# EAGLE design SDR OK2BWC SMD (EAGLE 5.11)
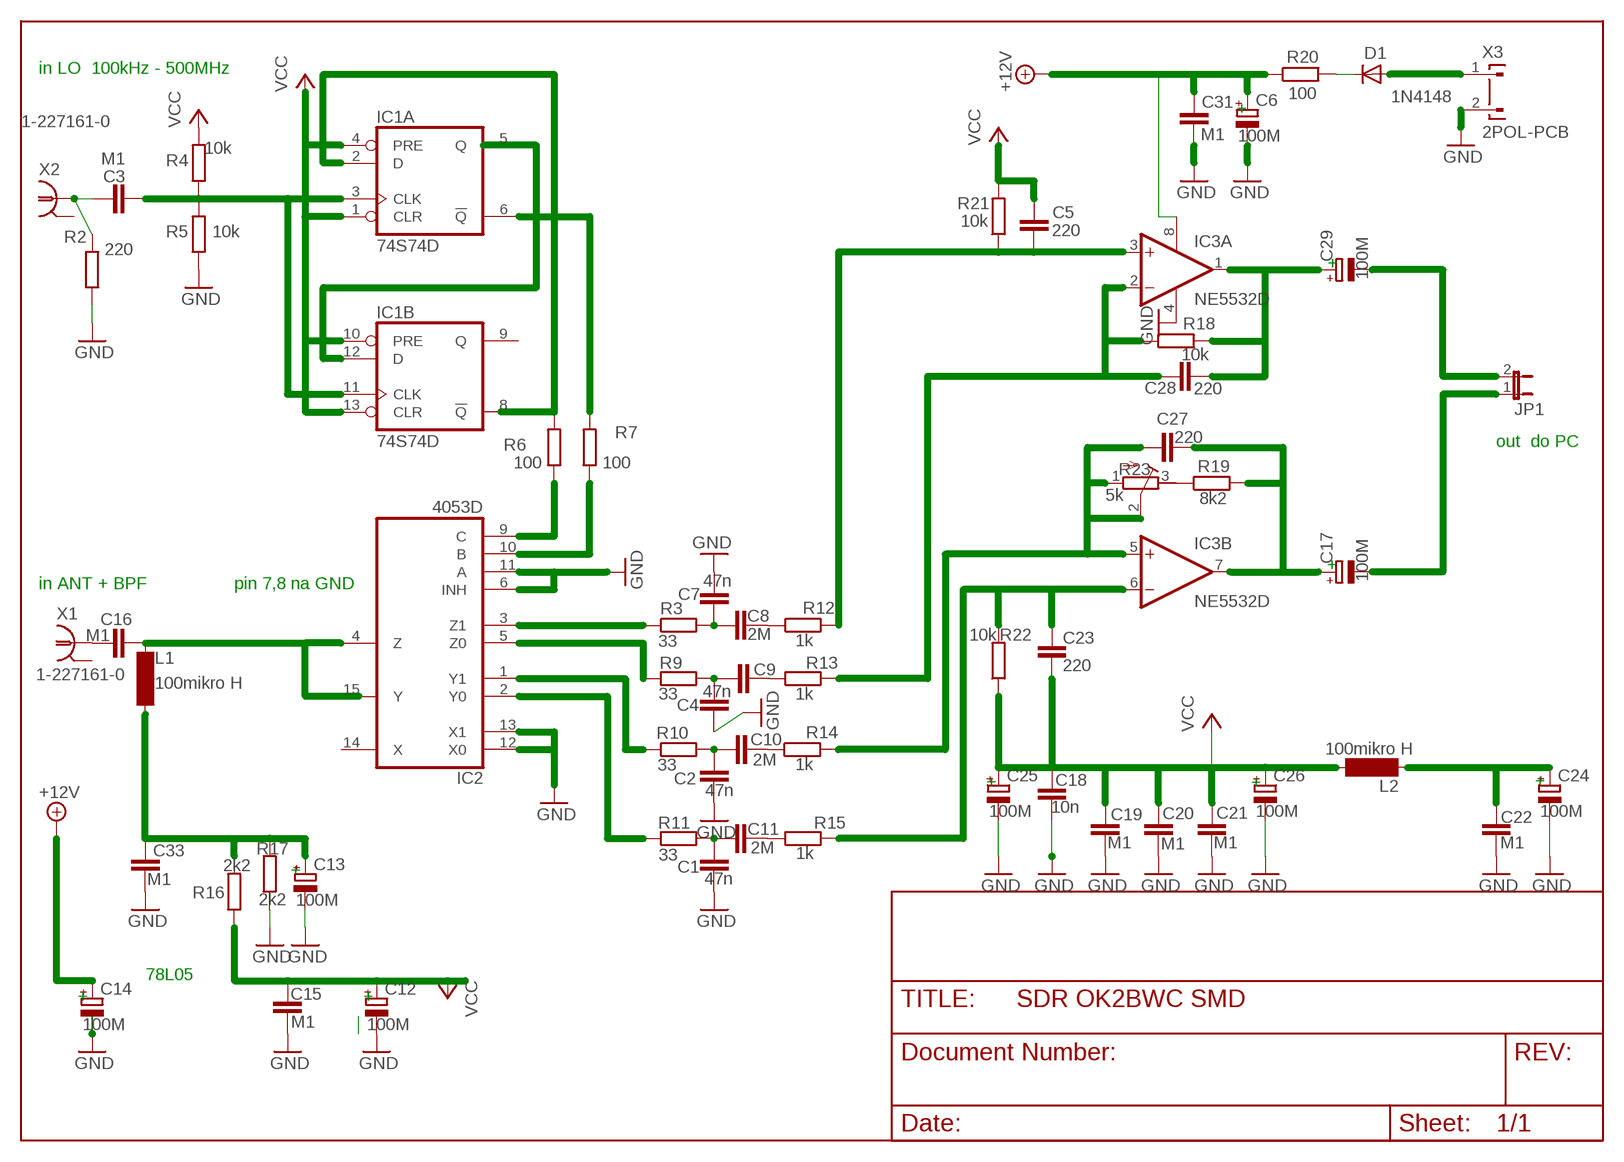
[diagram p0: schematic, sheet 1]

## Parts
C1  47n  C-EUC4532  [C4532]
C2  47n  C-EUC4532  [C4532]
C3  M1  C-EUC4532  [C4532]
C4  47n  C-EUC4532  [C4532]
C5  220  C-EUC4532  [C4532]
C6  100M  CPOL-EU085CS-1AR  [085CS_1AR]
C7  47n  C-EUC4532  [C4532]
C8  2M  C-EUC4532  [C4532]
C9  2M  C-EUC4532  [C4532]
C10  2M  C-EUC4532  [C4532]
C11  2M  C-EUC4532  [C4532]
C12  100M  CPOL-EU085CS-1AR  [085CS_1AR]
C13  100M  CPOL-EU085CS-1AR  [085CS_1AR]
C14  100M  CPOL-EU085CS-1AR  [085CS_1AR]
C15  M1  C-EUC2220K  [C2220K]
C16  M1  C-EUC4532  [C4532]
C17  100M  CPOL-EU085CS-1AR  [085CS_1AR]
C18  10n  C-EUC4532  [C4532]
C19  M1  C-EUC4532  [C4532]
C20  M1  C-EUC4532  [C4532]
C21  M1  C-EUC4532  [C4532]
C22  M1  C-EUC4532  [C4532]
C23  220  C-EUC4532  [C4532]
C24  100M  CPOL-EU085CS-1AR  [085CS_1AR]
C25  100M  CPOL-EU085CS-1AR  [085CS_1AR]
C26  100M  CPOL-EU085CS-1AR  [085CS_1AR]
C27  220  C-EUC4532  [C4532]
C28  220  C-EUC4532  [C4532]
C29  100M  CPOL-EU085CS-1AR  [085CS_1AR]
C31  M1  C-EUC4532  [C4532]
C33  M1  C-EUC2220K  [C2220K]
D1  1N4148  1N4148DO35-10  [DO35-10]
IC1  74S74D  [SO14]
IC2  4053D  [SO16]
IC3  NE5532D  [SO08]
JP1  JP1E  [JP1]
L1  100mikro H  SM-NE45  [SM-NE45]
L2  100mikro H  SM-NE45  [SM-NE45]
R2  220  R-EU_M3516  [M3516]
R3  33  R-EU_M3516  [M3516]
R4  10k  R-EU_M3516  [M3516]
R5  10k  R-EU_M3516  [M3516]
R6  100  R-EU_M3516  [M3516]
R7  100  R-EU_M3516  [M3516]
R9  33  R-EU_M3516  [M3516]
R10  33  R-EU_M3516  [M3516]
R11  33  R-EU_M3516  [M3516]
R12  1k  R-EU_M3516  [M3516]
R13  1k  R-EU_M3516  [M3516]
R14  1k  R-EU_M3516  [M3516]
R15  1k  R-EU_M3516  [M3516]
R16  2k2  R-EU_M3516  [M3516]
R17  2k2  R-EU_M3516  [M3516]
R18  10k  R-EU_M3516  [M3516]
R19  8k2  R-EU_M3516  [M3516]
R20  100  R-EU_M3516  [M3516]
R21  10k  R-EU_M3516  [M3516]
R22  10k  R-EU_M3516  [M3516]
R23  5k  R-TRIMM4G/J  [RTRIM4G/J]
X1  1-227161-0  [AMP_227161]
X2  1-227161-0  [AMP_227161]
X3  2POL-PCB  [2POL-PCB]

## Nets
+12V: C6.+ C14.+ C31.1 IC3.8(P:V+) R20.1
GND: C1.2 C2.2 C4.2 C6.- C7.1 C12.- C13.- C14.- C15.2 C18.2 C19.2 C20.2 C21.2 C22.2 C24.- C25.- C26.- C31.2 C33.2 IC2.6(INH) IC2.11(A) IC2.13(X1) IC3.4(P:V-) R2.1 R5.1 R17.1 X3.2
N$1: C3.1 R2.2 X2.1
N$2: IC1.5(A:Q) IC1.12(B:D)
N$3: C16.1 X1.1
N$4: C3.2 IC1.3(A:CLK) IC1.11(B:CLK) R4.1 R5.2
N$5: C16.2 IC2.4(Z) L1.2
N$6: IC2.9(C) R6.1
N$7: IC2.10(B) R7.1
N$8: IC1.6(A:!Q) R7.2
N$9: IC1.2(A:D) IC1.8(B:!Q) R6.2
N$10: C28.2 C29.+ IC3.1(A:OUT) R18.2
N$11: C17.+ C27.2 R19.2
N$12: C29.- JP1.2
N$13: C17.- JP1.1
N$14: D1.A X3.1
N$89: IC2.12(X0)
N$90: C7.2 C8.1 R3.2
N$91: C1.1 C11.1 R11.2
N$92: C2.1 C10.1 R10.2
N$93: C4.1 C9.1 R9.2
N$94: IC2.3(Z1) R3.1
N$95: IC2.5(Z0) R9.1
N$96: IC2.1(Y1) R10.1
N$97: IC2.2(Y0) R11.1
N$98: C8.2 R12.1
N$99: C9.2 R13.1
N$100: C10.2 R14.1
N$101: C11.2 R15.1
N$102: C13.+ C33.1 L1.1 R16.2 R17.2
N$103: D1.C R20.2
N$104: C28.1 IC3.2(A:-IN) R13.2 R18.1
N$106: R19.1 R23.3(A)
N$107: C27.1 R14.2 R23.1(E) R23.2(S)
N$108: C23.1 IC3.6(B:-IN) R15.2 R22.2
N$110: C22.1 C24.+ L2.1
N$111: C5.2 IC3.3(A:+IN) R12.2 R21.1
VCC: C5.1 C12.+ C15.1 C18.1 C19.1 C20.1 C21.1 C23.2 C25.+ C26.+ IC1.1(A:CLR) IC1.4(A:PRE) IC1.10(B:PRE) IC1.13(B:CLR) L2.2 R4.2 R16.1 R21.2 R22.1
Unconnected: IC1.9(B:Q) IC2.14(X) IC2.15(Y) IC3.5(B:+IN) IC3.7(B:OUT)

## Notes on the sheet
- in LO  100kHz - 500MHz
- +
- +
- out  do PC
- +
- in ANT + BPF | pin 7,8 na GND
- + | + | +
- +
- 78L05
- + | +

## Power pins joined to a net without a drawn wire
GND: IC1.7(P:GND) IC2.8(GND) X1.2(GND) X2.2(GND)
VCC: IC1.14(P:VCC) IC2.16(VCC)
VEE: IC2.7(VEE)

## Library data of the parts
C1-C5 C7-C11 C16 C18-C23 C27 C28 C31 = resistor:C-EU: CAPACITOR, European symbol
C6 C12-C14 C17 C24-C26 C29 = rcl:CPOL-EU: POLARIZED CAPACITOR, European symbol
C15 C33 = rcl:C-EU: CAPACITOR, European symbol
D1 = diode:1N4148: DIODE
IC1 = 74xx-eu:74*74: Dual D type positive edge triggered FLIP FLOP, preset and clear
IC2 = 40xx:4053: Triple 2-channel ANALOG MULTIPLEXER
IC3 = linear:NE5532: AUDIO AMPLIFIER
JP1 = jumper:JP1E: JUMPER
L1 L2 = inductor-neosid:SM-NE45: INDUCTOR; OC_FARNELL: unknown; OC_NEWARK: unknown
R2-R7 R9-R22 = resistor:R-EU_: RESISTOR, European symbol
R23 = rcl:R-TRIMM: Trimm resistor
X1 X2 = con-coax:?227161*: JACK, RIGHT ANGLE, 50 OHM, PCB, BNC; MF: TYCO ELECTRONICS; MPN: 1-227161; OC_FARNELL: unknown; OC_NEWARK: 33B3200
X3 = con-friwo:2POL-PCB: PCB SUPPLY CONNECTOR; OC_FARNELL: unknown; OC_NEWARK: unknown

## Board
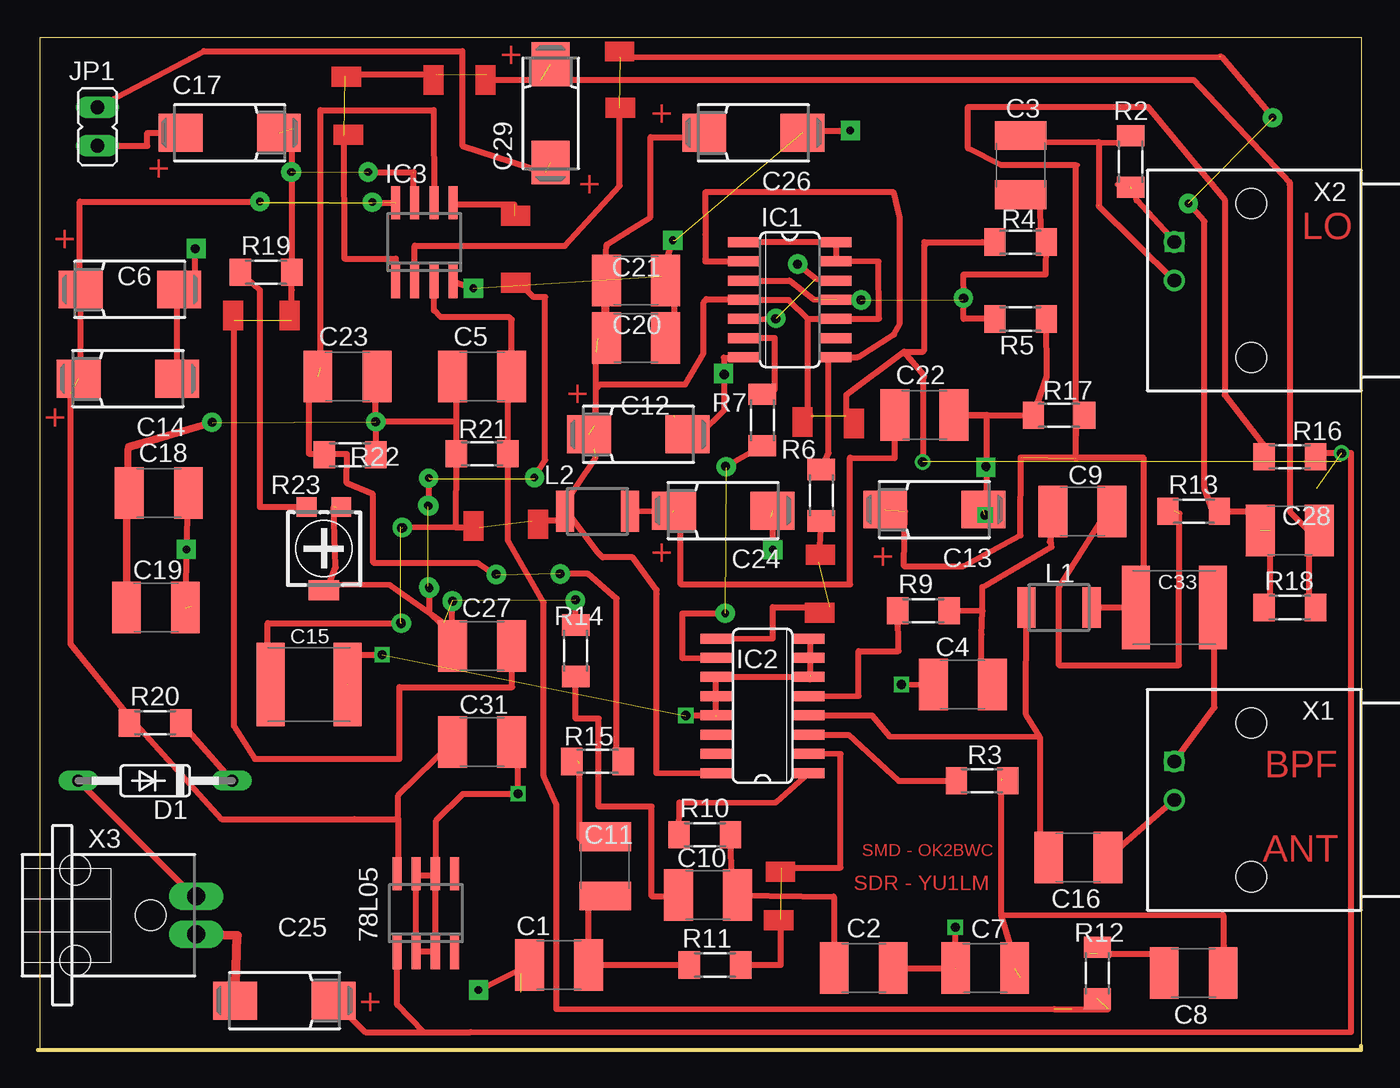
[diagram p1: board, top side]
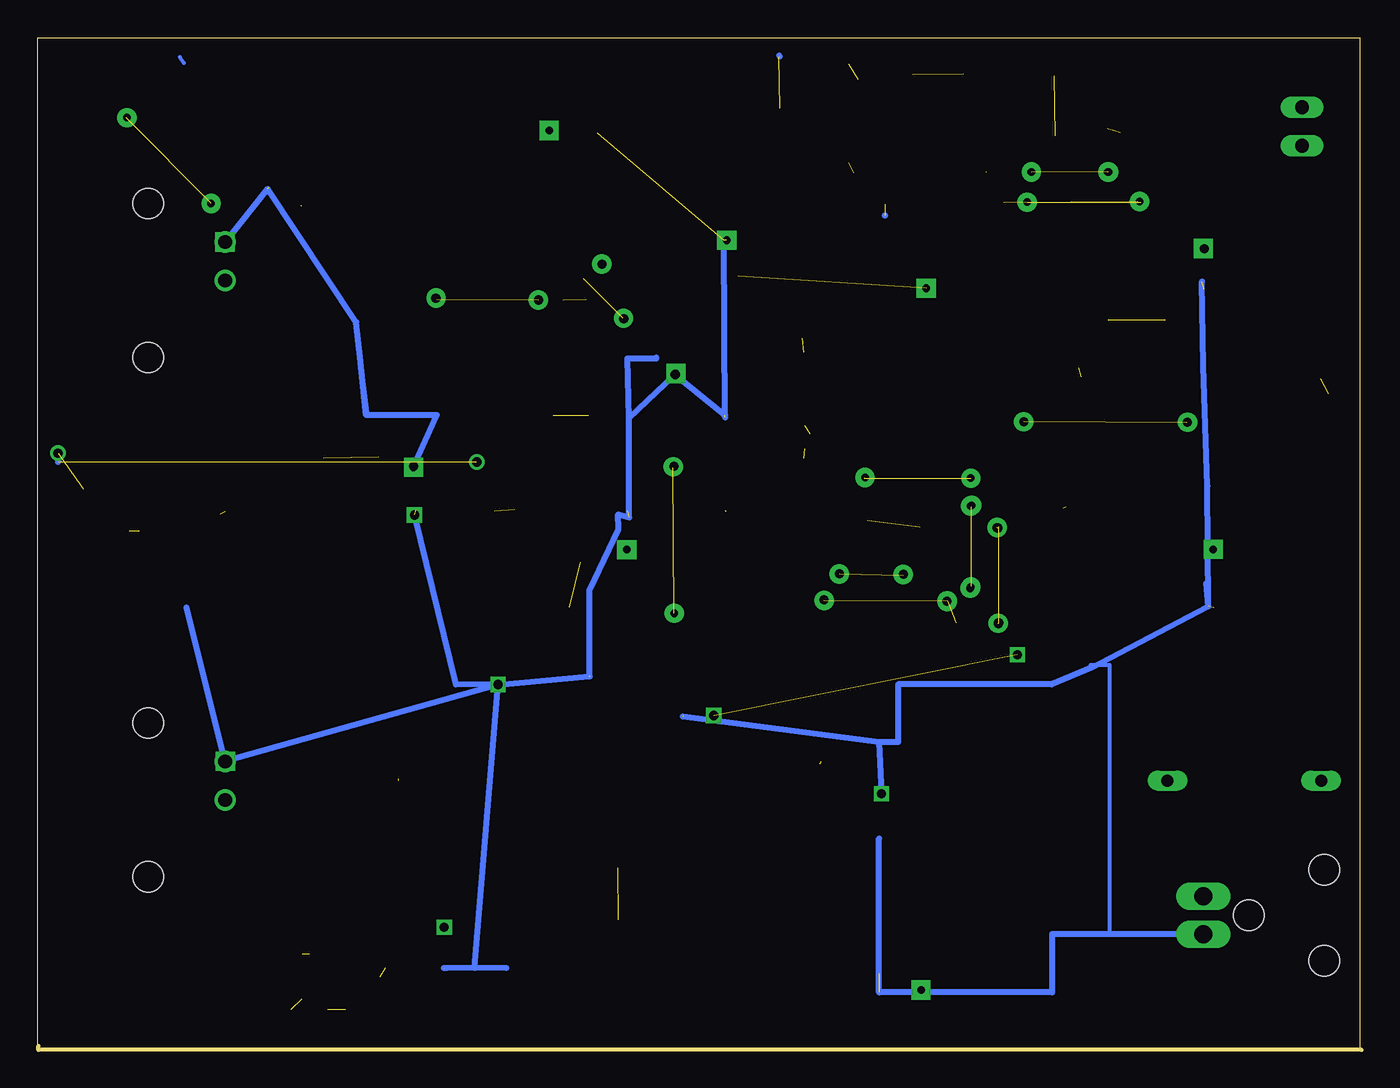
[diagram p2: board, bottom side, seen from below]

Size 87.43 x 66.82 mm. Coordinates in mm from the lower left corner, seen from the top.
Outline: 87.43,0 87.43,66.82 0.13,66.82 0.13,0
Outline: 0,0 87.39,0 87.39,0.26
Copper layers (1*16): Top 0.035mm / dielectric 1.5mm / Bottom 0.035mm
Design rules "default": minimum track width 10mil, minimum drill 24mil, track to track 8mil, track to pad 8mil, pad to pad 8mil, via to via 8mil, smd to smd 8mil, copper to edge 40mil, drill to drill 8mil, minimum pad ring 10mil, minimum via ring 8mil, stop-mask expansion 4mil, vias tented up to drill 0mil, thermal gap 10mil

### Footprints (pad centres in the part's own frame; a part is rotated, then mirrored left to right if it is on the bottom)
SO8 = smd 0.6 x 2.2: 1 -1.905,-2.6; 2 -0.635,-2.6; 3 0.635,-2.6; 4 1.905,-2.6; 5 1.905,2.6; 6 0.635,2.6; 7 -0.635,2.6; 8 -1.905,2.6
C4532 = smd 1.9 x 3.4: 1 -1.95,0; 2 1.95,0
085CS_1AR = smd 2.9 x 2.5: + 3.25,0; - -3.25,0
C2220K = smd 1.85 x 5.5: 1 -2.55,0; 2 2.55,0
DO35-10 = drill 0.813 long: A 5.08,0; C -5.08,0
SO14 = smd 0.66 x 2.032: 1 -3.81,-3.073; 2 -2.54,-3.073; 3 -1.27,-3.073; 4 0,-3.073; 5 1.27,-3.073; 6 2.54,-3.073; 7 3.81,-3.073; 8 3.81,3.073; 9 2.54,3.073; 10 1.27,3.073; 11 0,3.073; 12 -1.27,3.073; 13 -2.54,3.073; 14 -3.81,3.073
SO16 = smd 0.66 x 2.032: 1 -4.445,-3.073; 2 -3.175,-3.073; 3 -1.905,-3.073; 4 -0.635,-3.073; 5 0.635,-3.073; 6 1.905,-3.073; 7 3.175,-3.073; 8 4.445,-3.073; 9 4.445,3.073; 10 3.175,3.073; 11 1.905,3.073; 12 0.635,3.073; 13 -0.635,3.073; 14 -1.905,3.073; 15 -3.175,3.073; 16 -4.445,3.073
SO08 = smd 0.6 x 2.2: 1 -1.905,-2.6; 2 -0.635,-2.6; 3 0.635,-2.6; 4 1.905,-2.6; 5 1.905,2.6; 6 0.635,2.6; 7 -0.635,2.6; 8 -1.905,2.6
JP1 = drill 0.914 long: 1 0,-1.27; 2 0,1.27
SM-NE45 = smd 1.2 x 2.7: 1 -2.15,0; 2 2.15,0
M3516 = smd 1.4 x 1.8: 1 -1.7,0; 2 1.7,0
RTRIM4G/J = smd 1.3 x 1.3: 1 -1.15,-2.75; 3 1.15,-2.75 | smd 2 x 1.3: 2 0,2.75
AMP_227161 = drill 0.9 pad 1.27 round: 1 0,-5.08; 2 -2.54,-5.08 | hole 2: -5.08,0; 5.08,0
2POL-PCB = drill 1.2 long: 1 -1.25,11.6; 2 1.25,11.6 | hole 2: -3,3.6; 3,3.6; 0,8.6

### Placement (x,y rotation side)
78L05  [SO8]  25.62,9.03 0 top
C1  34.42,5.61 180 top
C2  54.54,5.41 0 top
C3  64.9,58.42 270 top
C4  61.09,24.13 180 top
C5  29.34,44.45 0 top
C6  6.08,50.21 180 top
C7  62.56,5.41 0 top
C8  76.33,5.08 180 top
C9  68.99,35.56 0 top
C10  44.26,10.23 180 top
C11  37.46,12.12 90 top
C12  39.66,40.64 180 top
C13  59.21,35.68 180 top
C14  5.95,44.32 180 top
C15  17.91,24.13 0 top
C16  68.71,12.7 180 top
C17  12.67,60.55 0 top
C18  7.99,36.77 0 top
C19  7.8,29.21 0 top
C20  39.5,46.99 0 top
C21  39.5,50.8 0 top
C22  58.55,41.91 0 top
C23  20.45,44.45 0 top
C24  45.26,35.61 180 top
C25  16.29,3.26 0 top
C26  47.26,60.55 180 top
C27  29.34,26.67 0 top
C28  82.68,34.29 0 top
C29  33.87,61.84 90 top
C31  29.34,20.32 0 top
C33  75.06,29.21 0 top
D1  7.75,17.78 180 top
IC1  49.66,49.53 270 top
IC2  47.87,22.72 90 top
IC3  25.53,53.34 0 top
JP1  3.94,60.96 0 top
L1  67.44,29.21 180 top
L2  36.96,35.56 180 top
R2  72.17,58.65 90 top
R3  62.36,17.78 0 top
R4  64.9,53.34 180 top
R5  64.9,48.26 180 top
R6  51.74,36.62 90 top
R7  47.85,41.59 90 top
R9  58.49,29 0 top
R10  44.05,14.21 0 top
R11  44.72,5.61 180 top
R12  69.98,5.08 270 top
R13  76.33,35.56 0 top
R14  35.52,26.36 90 top
R15  36.96,19.05 0 top
R16  82.68,39.17 180 top
R17  67.44,41.91 0 top
R18  82.68,29.21 0 top
R19  15.08,51.34 0 top
R20  7.75,21.59 0 top
R21  29.34,39.37 180 top
R22  20.62,39.3 180 top
R23  18.9,33.1 180 top
X1  80.14,16.51 270 top
X2  80.14,50.8 270 top
X3  -1.14,8.89 270 top

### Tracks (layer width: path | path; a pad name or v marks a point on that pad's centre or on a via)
+12V  (2 unrouted)
  Top 0.254: C31.1 26.8,20.32 | 5.9,22.17 6.48,21.59 R20.1
  Top 0.406: 2.17,43.32 2.17,26.79 5.9,22.17 12.14,15.24 20.91,15.24 20.94,15.22 23.75,15.22 23.8,15.26 | C14.+ 2.83,44.32 C6.+ 2.78,50.21 2.78,56.01 14.78,56.01 | 23.8,15.26 23.8,12.34 | 23.8,15.26 23.8,16.8 C31.1
GND  (via drill 0.6, 0.61)  (14 unrouted)
  Top 0.254: C20.2 42.04,46.99 | C1.2 31.88,5.08 | C19.2 9.02,29.21 | 9.92,36.9 C18.2 9.87,36.77 | C7.1 59.82,6.35 | R2.1 71.25,57.15 | R5.1 66.17,48.26 | R17.1 66.17,41.91 | 31.71,20.35 C31.2 30.61,20.32 | C4.2 v57.04,24.13 | C33.2
  Top 0.406: 32.55,5.61 C1.2 29.03,3.92 | 31.88,5.08 31.85,6.11 | v57.03,24.12 C4.2 | C33.2 77.7,29.21 77.7,22.62 X1.2 | IC2.8 51.02,27.16 51.02,24.69 51.05,24.49 | 51.05,24.49 50.94,24.49 IC2.6 | IC2.6 51.05,24.62 51.05,24.49 | v31.72,16.92 31.71,20.35 | 42.04,46.99 42.04,50.21 C21.2 41.45,50.82 41.18,51.09 41.94,53.46 | 60.59,8.16 C7.1 C2.2 | R5.1 66.64,44.44 R17.1 C22.2 62.68,41.93 62.68,38.44 | IC3.4 28.76,50.28 | IC2.6 IC2.11 44.79,24.62 44.8,23.48 | 42.7,22.09 44.8,22.09 | 44.8,23.48 44.8,24.67 | 44.8,22.09 IC2.13 | 44.8,22.09 44.8,23.48 | C14.- 9.2,50.21 C6.- 10.39,50.21 v10.39,52.89 | C26.- 50.64,60.68 53.7,60.68 | 45.32,44.52 45.26,44.65 | 45.32,44.52 45.32,42.25 43.71,40.64 C12.- | IC1.7 46.58,45.71 45.31,45.71 45.34,45.68 v45.34,44.59 45.34,44.54 45.32,44.52 | 48.54,33.06 C24.- | 62.68,38.44 62.68,37.02 C13.- | v62.62,38.53 62.23,38.6 62.49,38.34 62.68,38.44 | C19.2 9.92,36.9 | C15.2 20.47,26.1
  Top 0.61: C25.- 13.17,7.55 X3.2
  Bottom 0.254: 16.64,7.62 16.64,7.64 16.64,25.4 17.91,25.4 17.84,25.24 | 66.15,45.72 65.7,42.1
  Bottom 0.406: X3.2 16.64,7.64 20.45,7.64 20.45,3.81 31.88,3.81 31.88,13.97 | 31.88,20.32 v31.72,16.92 | 31.88,20.32 30.61,20.32 30.61,24.13 C15.2 17.84,25.24 10.14,29.28 | 10.14,29.28 10.19,37.23 10.47,45.17 10.54,50.72 | 10.14,29.28 10.27,30.81 | 31.88,20.32 44.83,22.02 | 48.37,41.72 48.37,35.16 49.1,35.36 49.09,34.4 51,30.38 50.98,24.66 v57.03,24.12 | 48.37,41.72 48.5,45.66 46.59,45.66 IC1.7 | 48.37,41.72 v45.34,44.59 42.04,41.91 | v62.62,38.53 61.09,41.91 R17.1 66.15,45.72 66.4,48.06 72.24,56.85 X2.2 | v62.56,35.32 59.82,24.13 v57.03,24.12 | 58.58,5.42 60.42,5.41 C7.1 | v57.03,24.12 X1.2 C33.2 | C2.2 58.58,5.42 | 42.04,41.76 42.13,53.45 | 58.58,5.42 v57.03,24.12
N$1  (1 unrouted)
  Top 0.254: C3.1 64.86,59.96
  Top 0.406: 64.86,59.96 70.07,59.93 | 70.07,59.93 72.07,59.91 R2.2 72.11,60.44 71.78,60.21 71.45,59.84 | 70.07,59.93 70.09,55.76 | 70.05,55.74 X2.1
N$2  (via drill 0.6, 0.61)  (1 unrouted)
  Top 0.254: v48.73,48.27 IC1.5
  Top 0.406: IC1.12 51.38,50.93 v50.17,51.88 | v48.73,48.27 47.25,48.25 48.79,48.3
N$3
  Top 0.254: C16.1 71.25,12.7
  Top 0.406: C16.1 X1.1
N$4  (via drill 0.61)  (2 unrouted)
  Top 0.254: 66.18,56.47 C3.2 | R4.1 66.27,53.34
  Top 0.406: 63.63,48.26 63.63,48.3 63.53,48.4 | 63.53,48.4 63.53,48.2 63.26,48.2 R5.2 61.13,48.26 v61.15,49.63 61.13,51.2 66.56,51.2 R4.1 | 63.53,48.4 63.33,48.6 | IC1.3 49.63,50.8 49.67,50.76 49.7,50.76 51.24,49.56 v54.36,49.51 | 66.27,53.34 66.18,56.47
  Bottom 0.254: v61.15,49.63 61.09,49.53
N$5
  Top 0.254: L1.2 64.9,29.21 | 66.17,12.7 C16.2
  Top 0.406: IC2.4 55.09,22.09 56.25,20.7 66.17,20.67 | 66.17,20.67 66.17,12.7 | 66.17,20.67 65.27,22.16 L1.2 | 64.9,29.21 65.07,29.23
N$6  (1 unrouted)
  Top 0.406: IC2.9 48.54,27.18 48.55,29.23 52.3,29.23 | 51.59,32.19 R6.1
N$7  (1 unrouted)
  Top 0.406: IC2.10 42.57,25.87 42.57,28.83 45.43,28.84 | R7.1 45.5,38.58 45.47,38.55 45.49,38.45
N$8
  Top 0.254: 45.85,46.99 IC1.6
  Top 0.406: 45.85,46.99 48.68,47 48.68,43.61 R7.2
N$9
  Top 0.254: R6.2 52.2,38.15 | 52.2,45.59 IC1.8 53.47,45.72 | 44.08,56.62 44.06,55.14 | 45.85,52.07 IC1.2
  Top 0.406: 45.85,52.07 44.09,52.07 44.08,52.21 44.08,53.82 44.08,56.62 56.53,56.62 56.92,54.94 56.92,47.95 56.54,47.24 54.16,45.75 53.59,45.72 53.47,45.72 | R6.2 52.23,39.41 52.2,45.59
N$10  (3 unrouted)
  Top 0.254: 83.95,29.21 R18.2 | 83.95,34.29 C28.2
  Top 0.406: IC3.1 23.63,52.25 20.25,52.24 20.24,60.37 | 26.29,64.43 20.28,64.43 20.28,64.31 | 82.67,57.3 76.33,64.04 33.22,64.06 29.63,64.06 29.63,64.4 | 82.67,57.3 82.68,57.15 | 83.95,29.21 83.95,34.29 82.7,35.55 82.67,57.3
N$11  (via drill 0.5 pad 1.27)  (5 unrouted)
  Top 0.406: C27.2 31.32,23.96 23.88,23.96 23.88,19.22 14.34,19.22 12.96,21.39 12.96,48.19 | 16.77,48.18 16.77,50.18 R19.2 16.78,60.81 v16.76,57.97 | v21.81,57.96 24.79,57.96 | 24.98,55.95 24.83,55.95 24.83,57.95
  Bottom 0.406: 21.94,58.08 21.94,57.96 v21.81,57.96 21.81,58.08
  other vias: 16.74,57.96
N$12  (1 unrouted)
  Top 0.406: JP1.2 10.98,65.94 28.03,65.95 28.03,59.71 33.52,57.92
N$13
  Top 0.406: C17.- 7.23,60.55 7.23,59.69 JP1.1
N$14
  Top 0.254: X3.1 10.29,10.16
  Top 0.406: 10.29,10.16 D1.A
N$15  (via drill 0.5)
  other vias: 75.06,50.79
N$16  (1 unrouted)
  Top 0.406: 22.09,55.94 23.67,55.95
  Bottom 0.406: 14.57,55.95 14.51,55.99
N$18
  Top 0.406: 75.13,53.33 72.57,56.09 72.3,57.15
N$19  (via drill 0.6)
  other vias: 30.27,31.4
N$20  (1 unrouted)
  Top 0.406: 27.47,55.82 31.47,55.82
  Bottom 0.406: 31.47,55.08 31.5,55.08
N$23  (via drill 0.6)  (1 unrouted)
  other vias: 24.03,34.46 24.09,34.47 24.03,34.46
N$24  (via drill 0.6)
  other vias: 27.38,29.62
N$25  (via drill 0.6)
  other vias: 35.5,29.72
N$26  (via drill 0.5 pad 1.27)
  other vias: 28.76,50.29
N$27  (via drill 0.6)
  other vias: 45.42,38.54
N$28  (via drill 0.5)
  other vias: 75.04,16.53
N$29  (via drill 0.5)
  other vias: 75.14,19.02
N$30  (via drill 0.5)
  other vias: 12.89,17.77
N$31  (via drill 0.5)
  other vias: 2.7,17.77
N$32  (via drill 0.5 pad 1.27)
  other vias: 10.39,10.2
N$33  (via drill 0.5 pad 1.27)
  other vias: 10.39,7.7
N$34  (via drill 0.5 pad 1.27)
  other vias: 24.01,28.17
N$35  (via drill 0.5 pad 1.27)
  other vias: 24.08,34.49
N$36  (via drill 0.5 pad 1.27)
  other vias: 45.4,28.83
N$37  (via drill 0.5 pad 1.27)
  other vias: 45.46,38.51
N$38  (via drill 0.5 pad 1.27)
  other vias: 81.55,61.55
N$39  (via drill 0.5 pad 1.27)
  other vias: 75.99,55.88
N$40  (via drill 0.5 pad 1.27)
  other vias: 61.12,49.64
N$41  (via drill 0.5 pad 1.27)
  other vias: 62.62,38.47
N$42  (via drill 0.5 pad 1.27)
  other vias: 75.04,19.06
N$43  (via drill 0.6)  (1 unrouted)
  Top 0.406: 20.55,26.08 20.47,24.17 20.41,24.2 | v22.73,26.09 21.19,26.1 20.55,26.08 | 20.55,26.08 20.54,26.04
  other vias: 42.79,22.08
N$44  (via drill 0.5 pad 1.27)
  other vias: 45.29,44.66
N$46  (via drill 0.5 pad 1.27)
  other vias: 48.54,33.03
N$47  (via drill 0.5 pad 1.27)
  other vias: 41.94,53.46
N$49  (via drill 0.5 pad 1.27)
  other vias: 50.18,51.89
N$50  (via drill 0.5 pad 1.27)
  other vias: 53.66,60.7
N$51  (via drill 0.5 pad 1.27)
  other vias: 16.72,57.96
N$52  (via drill 0.6)
  other vias: 60.59,8.1
N$54  (via drill 0.5 pad 1.27)
  other vias: 75.08,53.35
N$55  (via drill 0.6 pad 1.27)
  other vias: 11.5,41.45
N$56  (via drill 0.5 pad 1.27)
  other vias: 14.67,56.02
N$57  (via drill 0.5 pad 1.27)
  other vias: 22.1,55.97
N$58  (via drill 0.5 pad 1.27)
  other vias: 25.86,30.48
N$59  (via drill 0.5 pad 1.27)
  other vias: 27.37,29.61
N$60  (via drill 0.5 pad 1.27)
  other vias: 30.28,31.39
N$61  (via drill 0.5 pad 1.27)
  other vias: 34.5,31.42
N$62  (via drill 0.5 pad 1.27)
  other vias: 35.5,29.68
N$63  (via drill 0.5 pad 1.27)
  other vias: 25.81,37.75
N$64  (via drill 0.5 pad 1.27)
  other vias: 32.8,37.79
N$65  (via drill 0.5 pad 1.27)
  other vias: 25.76,35.96
N$66  (via drill 0.5 pad 1.27)
  other vias: 54.38,49.51
N$67  (via drill 0.5 pad 1.27)
  other vias: 48.75,48.3
N$68
  Top 0.406: 26.28,5.74 26.31,5.74 26.28,6.52 25.05,6.52 | 25.05,6.52 24.99,6.52 | 24.99,11.06 24.99,6.58 25.05,6.52
N$69
  Top 0.406: 26.28,11.52 26.28,6.32 26.31,6.29
N$70
  Top 0.406: 26.31,12.45 26.25,11.55 24.96,11.55
N$71
  Top 0.406: 26.31,11.84 26.31,15.16 28.08,16.9 31.76,16.9 | 31.76,16.9 31.76,16.81 31.82,16.81 31.82,16.84 | 31.76,16.9 31.76,16.93
N$90  (2 unrouted)
  Top 0.254: R3.2 63.63,17.78 | 78.29,8.9 78.2,8.96 78.52,5.34 C8.1
  Top 0.406: 63.63,8.92 63.63,8.9 64.87,4.81 | 63.63,8.92 63.64,17.91 | 63.63,8.92 78.29,8.9 78.29,4.41
N$91
  Top 0.254: R11.2 43.08,5.69
  Top 0.406: C11.1 36.37,9.48 C1.1 R11.2
N$92
  Top 0.254: R10.2 45.85,14.31 | 45.85,10.16 45.85,10.96 C10.1
  Top 0.406: C2.1 52.57,10.13 C10.1 | 45.85,10.96 R10.2
N$93
  Top 0.254: 66.77,33.54 66.86,34.47 C9.1 | C4.1 62.36,24.13
  Top 0.406: 62.36,24.13 62.33,27.42 62.39,28.98 | 62.39,28.98 R9.2 | 62.39,28.98 62.37,30.56 66.94,33.22 66.86,34.47
N$94
  Top 0.406: IC2.3 53.55,20.8 56.84,17.77 R3.1
N$95
  Top 0.406: R9.1 56.84,26.33 54.21,26.33 54.21,23.37 IC2.5
N$96
  Top 0.406: R10.1 42.37,16.33 48.78,16.37 IC2.1
N$97  (1 unrouted)
  Top 0.406: R11.1 49.07,5.62 49.07,8.61 | IC2.2 53.02,19.53 53.02,12.03 49.1,12.03 49.14,12.09
N$98  (1 unrouted)
  Top 0.254: 73.79,6.35 73.79,5.08 C8.2 | R12.1 69.98,6.35
  Top 0.406: 69.48,6.35 73.79,6.35
N$99  (1 unrouted)
  Top 0.254: 75.17,35.08 75.06,35.56 R13.1 | 70.33,35.09 C9.2
  Top 0.406: 70.33,35.09 67.44,30.53 67.44,25.4 75.37,25.4 75.4,35.41
N$100
  Top 0.254: R14.1 35.56,24.58 | 42.22,10.16 C10.2
  Top 0.406: 42.22,10.16 40.53,10.16 40.53,16.06 37.04,16.06 37.04,21.88 35.52,21.88 R14.1
N$101  (1 unrouted)
  Top 0.254: R15.1 35.69,19.05 | C11.2 37.71,14.03
  Top 0.406: 37.71,14.03 35.79,13.97 35.79,18.89
N$102  (2 unrouted)
  Top 0.254: 73,29.4 C33.1 | 68.55,58.42 68.71,58.42 | 81.41,39.37 R16.2 | 68.56,39.06 68.71,41.91 R17.2
  Top 0.406: C33.1 L1.1 | 57.28,35.56 57.2,31.95 61.14,31.94 64.9,33.98 64.92,39.13 73,39.13 73,29.4 | 68.56,39.06 68.56,41.61 68.55,58.42 63.63,58.42 61.44,59.53 61.44,62.26 73.32,62.26 78.39,56.14 78.39,43.25 81.41,39.37
N$103
  Top 0.254: R20.2 9.02,21.59
  Top 0.406: R20.2 D1.C
N$104  (5 unrouted)
  Top 0.254: R18.1 81.41,29.21 | 80.14,35.56 80.14,34.29 C28.1 | R13.2 77.6,35.56
  Top 0.406: 38.42,62.17 38.42,57.06 34.79,53.08 24.89,53.08 24.89,53.1 IC3.2 | 38.49,65.54 78.19,65.57 | 77.6,35.56 77.04,37.13 77.04,54.71 75.99,55.89 | 78.19,65.57 81.58,61.56 | 78.19,65.57 78.09,65.58 | 81.41,29.21 81.41,34.29 | R13.2 80.14,35.56
  Bottom 0.254: 77.78,65.16 78.06,65.57
  Bottom 0.406: 38.46,65.64 38.42,65.58
N$106
  Top 0.254: R19.1 12.83,51.74
  Top 0.406: R23.3 14.67,35.85 14.67,50.17 R19.1
N$107  (via drill 0.5 pad 1.27)  (7 unrouted)
  Top 0.254: 19.73,35.73 19.74,35.8 R23.1 | 19.25,30.74 18.93,30.27 R23.2
  Top 0.406: C27.1 v27.37,29.66 | R14.2 35.5,29.69 | 19.54,35.88 19.67,31.86 19.25,30.74 23.24,30.71 26.8,28.19 26.56,28.19 25.87,28.88 25.87,30.5 v25.81,30.56 | 32.85,37.73 32.85,37.89 33.5,38.94 33.5,49.71 32.73,49.71 31.48,50.96 31.48,51.03 | v25.82,35.92 25.84,35.94 25.84,37.75
  Bottom 0.406: 32.82,37.71 32.88,37.77 | 25.82,37.73 25.84,37.71 | v25.82,35.92 25.76,35.86 | v25.81,30.56 25.76,30.61
N$108  (via drill 0.6)  (2 unrouted)
  Top 0.254: 38.23,18.94 38.23,19.05 R15.2 | 17.91,44.45 C23.1 | R22.2 18.3,39.34 17.91,39.37
  Top 0.406: 38.23,18.94 38.23,29.8 36.34,31.44 v34.48,31.43 | v34.48,31.43 34.46,31.4 | IC3.6 26.15,62.05 18.67,62.05 18.67,45.04 | 30.26,31.34 29.05,32.16 22.15,32.18 22.14,36.68 20.4,37.43 20.42,39.3 20.42,39.34 18.3,39.34 | v34.48,31.43 34.54,31.34 | 17.91,44.45 17.91,39.37 18.71,39.37
N$110  (1 unrouted)
  Top 0.254: 42.45,35.55 41.95,35.42 41.95,35.54
  Top 0.406: L2.1 42.21,35.49 41.95,35.42 | 42.45,35.55 42.46,30.75 53.64,30.74 53.64,39.11 56.6,39.07 C22.1
N$111  (2 unrouted)
  Top 0.254: C5.2 31.06,44.44 | 68.43,2.62 68.3,2.69 | R12.2 69.98,3.81 | R21.1 31.05,39.27
  Top 0.406: IC3.3 26.16,48.83 26.61,48.38 31.12,48.38 31.29,48.21 C5.2 31.05,44.21 31.05,39.27 | R21.1 31.04,33.63 33.41,29.54 33.41,18.06 34.25,16.17 34.25,2.71 67.11,2.7 70.7,2.7
S$1  (via drill 0.5 pad 1.27)
  other vias: 9.8,33.05
S$2  (via drill 0.5 pad 1.27)
  other vias: 10.45,52.92
S$3  (via drill 0.5 pad 1.27)
  other vias: 29.1,3.96
VCC  (via drill 0.6 pad 1.27, 0.61)  (11 unrouted)
  Top 0.254: IC1.10 53.47,48.26 | 53.47,52.07 IC1.13 | 63.63,53.34 R4.2 62.36,53.34 62.36,53.33 | 58.55,53.34 | IC1.4 45.85,49.53 | C15.1 15.17,24 | 57.21,46.11 58.55,44.45 | R16.1 83.95,39.37 | 34.42,35.56 L2.2 | C20.1 36.96,46.99 | 37.34,47.63 37.63,48.37 C20.1 | 37.34,47.63 37.43,51.04 | C23.2 22.99,44.45 | C20.1 37.34,47.63 | C25.+ 19.56,3.29
  Top 0.406: 63.33,53.33 62.36,53.33 58.55,53.34 58.64,53.21 58.55,53.12 58.55,46.22 58.46,46.11 57.21,46.11 | 84.73,39.4 84.53,39.2 R16.1 84.25,39.41 84.29,39.4 84.73,39.4 | 15.17,24 15.18,28.18 24.03,28.16 | IC2.16 40.85,18.3 40.86,30.09 40.86,30.36 39.28,32.52 37.3,32.52 36.97,32.85 34.87,35.63 34.71,35.39 | 27.62,34.51 R21.2 27.64,41.46 | C5.1 27.65,43.12 27.64,42.97 27.64,41.46 | 23.96,34.53 27.62,34.51 | 32.63,34.94 34.79,34.93 34.72,35.26 34.39,35.42 | 36.75,41.22 36.75,39.68 36.82,39.85 36.87,43.67 37.14,43.94 42.77,43.94 43.96,45.97 43.97,49.35 44.15,49.57 46.55,49.57 IC1.4 49.52,49.53 49.54,49.51 49.58,49.51 50.83,48.26 | 50.83,48.26 IC1.10 | 50.83,48.26 50.83,42.09 51.05,41.87 | IC1.14 IC1.1 | 53.47,48.26 54.22,48.26 55.55,48.29 55.53,52.05 53.47,52.07 | 53.4,41.88 53.4,43.23 53.42,43.25 57.21,46.11 | 57.21,46.11 58.49,44.57 | 27.62,34.51 29.17,34.5 | 34.42,35.56 34.42,35.69 34.71,35.39 | 34.71,35.39 34.39,35.42 | 34.39,35.42 36.82,39.07 36.85,46.08 | C20.1 37.55,50.61 37.57,50.63 | C21.1 37.43,51.04 37.57,53.17 38.92,54.01 40.46,54.98 40.48,60.26 | 40.48,60.26 40.48,60.17 | 27.64,41.46 v22.32,41.47 | C23.2 22.32,44.45 v22.32,41.47 | 5.95,39.84 5.95,36.98 | 58.55,44.45 58.48,44.38 58.44,44.38 v58.44,38.82 | C26.+ 43.72,60.26 40.48,60.26 | IC1.13 IC1.14 | IC1.14 52.7,53.39 | 25.48,1.17 21.63,1.17 C25.+ | 25.48,1.17 28.58,1.17 86.73,1.2 86.73,39.4 v86.1,39.4 84.73,39.4 | 25.48,1.17 23.74,2.97 23.74,6.27 | 5.95,39.84 6.01,39.73 | v22.32,41.47 R22.1 | 6,39.88 5.95,39.84 | 6,39.88 C18.1 5.85,36.58 C19.1 5.94,29.21 5.94,39.74 11.55,41.42 | 6,39.88 11.52,41.46
  Bottom 0.406: v22.32,41.47 22.39,41.42 22.32,41.42 v22.32,41.47 | v22.32,41.47 22.32,41.55 | v58.44,38.82 58.49,38.82 | v22.32,41.47 22.32,41.56 | v86.1,39.4 86.1,38.82
  other vias: 23.97,28.21 23.99,28.16
(copper drawn outside any net)
  shapes: Top area x18

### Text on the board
Top: + | + | + | + | LO | + | + | + | + | + | BPF | SMD - OK2BWC | ANT | SDR - YU1LM | +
